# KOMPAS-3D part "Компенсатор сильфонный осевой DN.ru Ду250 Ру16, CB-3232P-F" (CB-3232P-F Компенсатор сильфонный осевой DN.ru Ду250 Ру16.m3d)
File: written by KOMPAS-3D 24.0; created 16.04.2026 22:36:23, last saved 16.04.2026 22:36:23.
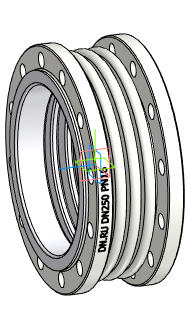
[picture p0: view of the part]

Document properties: Автор: DN.RU; Полное имя файла: D:\PROJECT CAD\DN.RU\..199(ACTUALE). CB-3232P-F Компенсатор сильфонный осевой DN.ru\Исходники\DN250\CB-3232P-F Компенсатор сильфонный осевой DN.ru Ду250 Ру16.m3d

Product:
- Body: Твердое тело1  | qty 1
    Масса: 37.919711
- Part/product: Компенсатор сильфонный осевой DN.ru Ду250 Ру16  | designation CB-3232P-F
    Масса: 29.4
    Раздел спецификации: Прочие изделия
    Комментарий: D140-02145
    Примечание: D140-02145
    additional columns: Типовые

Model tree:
1. Твердое тело1  (labels: Твердое тело1)

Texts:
  CB-3232P-F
